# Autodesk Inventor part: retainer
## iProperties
Created: 2001-11
Part Number: retainer
Document SubType Name: Modeling
Designer: hassen
Density: 1 g/cm^3
Control State: 0
Master: False
Checked Out: False
Shininess: 64.0
Length Units: 11269
Angle Units: 11279
Time Units: 11290
Mass Units: 11283
Length Display Precision: 3
Angle Display Precision: 2
Density: 0.0
Volumn: 0.0
Area: 0.0
PropertySet Name: Model Information
Author: hassen
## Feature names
1. Extrusion1
